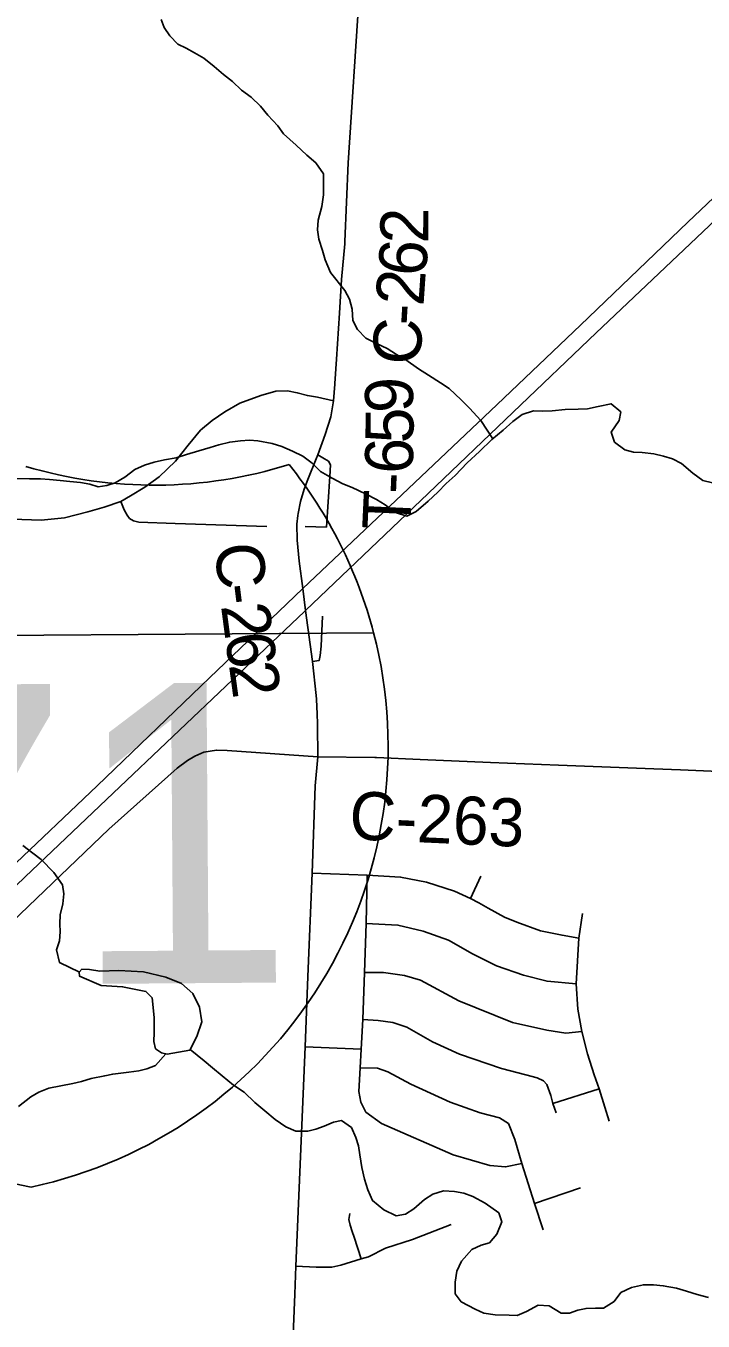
# Model space of a CAD drawing. Extents: x 114604 to 551442, y 316898 to 567001.
# Drawn here: x 184266 to 188495, y 344546 to 352635 of the extents above; entities that cross this region are included whole.
import ezdxf

# ---------------------------------------------------------------- set-up
doc = ezdxf.new("R2010")
doc.units = 0
for name, color, linetype in [('GE_P_Alignment', 7, 'Continuous'), ('GE_P_Alignment_1000_Cardinal_Points', 7, 'Continuous'), ('GE_P_Alignment_100_Cardinal_Points', 7, 'Continuous'), ('GE_P_Alignment_500_Bearings', 7, 'Continuous'), ('GE_P_Alignment_500_Stations', 7, 'Continuous'), ('MT_X_Edge_Line', 7, 'Continuous'), ('PM_P_Cells', 7, 'Continuous'), ('PM_P_CL_Double_Solid', 7, 'Continuous'), ('PM_P_Crosswalk', 7, 'Continuous'), ('PM_X_Stop_Line', 7, 'Continuous')]:
    doc.layers.add(name, color=color, linetype=linetype)

msp = doc.modelspace()

# ---------------------------------------------------------------- linework, layer by layer
at = {"layer": 'GE_P_Alignment'}
for p, q in [((182108.8, 348813.2), (186437.4, 348844.4)), ((186437.4, 348844.4), (182108.8, 348813.2)), ((186437.4, 348844.4), (182108.8, 348813.2))]:
    msp.add_line(p, q, dxfattribs=at)
for centre, start, end in [((185068, 352579.4), 253.42198, 287.40383), ((183715.5, 348135.1), 14.60627, 38.74396), ((184840.6, 348143.2), 166.21952, 258.87591), ((183715.5, 348135.1), 281.94987, 14.60626)]:
    msp.add_arc(centre, 2812.7, start, end, dxfattribs=at)
at = {"layer": 'GE_P_Alignment_1000_Cardinal_Points'}
msp.add_line((186010.5, 349509.4), (186142.5, 349503.5), dxfattribs=at)
for points in [[(186142.5, 349503.5), (186162.9, 349821.6), (186167.1, 349894.3), (186154.7, 349915.6), (186120.8, 349936.8), (186089.1, 349956.4)], [(186056.5, 348666), (186097.3, 348671.5), (186104, 348703.6), (186109.6, 348761), (186117.8, 348949.4)]]:
    msp.add_lwpolyline(points, dxfattribs=at)
at = {"layer": 'GE_P_Alignment_100_Cardinal_Points'}
for p, q in [((187042, 347184.6), (187106.8, 347325.2)), ((186009.6, 346258.3), (186358.7, 346245.2)), ((187556.9, 345905.7), (187846.2, 345996.4)), ((187442.7, 345281.3), (187729.1, 345377.4))]:
    msp.add_line(p, q, dxfattribs=at)
for points in [[(184859.5, 349665.4), (184880.1, 349612.7), (184897.1, 349579.2), (184913, 349559.3), (184937.3, 349544.8), (184971, 349535.6), (185197.9, 349527.8), (185769.5, 349508.8)], [(182825.3, 344498.5), (183312.3, 345163.3), (183352.2, 345250.6), (183357.3, 345349.2), (183381, 345685.8), (183381.3, 346045.3), (183386.5, 346123.7), (183420.8, 346199.3), (184129.2, 346991), (184784.2, 347618.1), (185210.8, 347999.8), (185274.8, 348047), (185321.4, 348074.7), (185377.9, 348098.5), (185455.8, 348112.7), (185522.2, 348109.3), (186088.3, 348070.5)], [(186053, 347342.9), (186397.5, 347331.9), (186605.9, 347318.6), (186767, 347286.4), (186942.3, 347231.3), (187042, 347184.6), (187094.1, 347158.3), (187152.9, 347125.3), (187254.9, 347069.7), (187332.2, 347038.3), (187479.4, 346983), (187614.5, 346955.8), (187718.6, 346937)], [(187363.5, 345530.9), (187261.6, 345509.1), (187162.3, 345517.4), (186933.5, 345584.9), (186487.5, 345780), (186387.8, 345851.4), (186357.3, 345914.4), (186344.8, 345980.4), (186352.7, 346127.7), (186358.7, 346245.2), (186370.4, 346430.1), (186381.5, 346723), (186391.2, 347029.3), (186397.5, 347331.9)], [(187907.7, 345795.5), (187881.5, 345882.5), (187846.2, 345996.4), (187814, 346083.4), (187774, 346215.3), (187738.4, 346354.8), (187713.4, 346494.4), (187702.1, 346652.3), (187718.6, 346937), (187742.9, 347092.6)], [(186391.2, 347029.3), (186589.7, 347019.1), (186746.2, 346981.1), (186905.8, 346925.2), (187054.4, 346839.8), (187204.4, 346765), (187373.1, 346706.1), (187520.6, 346668.1), (187702.1, 346652.3)], [(186381.5, 346723), (186498.7, 346723.8), (186631, 346703.8), (186730.4, 346674.4), (186968.7, 346546.9), (187303.9, 346411.8), (187519, 346363.8), (187637.9, 346345.1), (187738.4, 346354.8)], [(187576.8, 345847.2), (187556.9, 345905.7), (187544.5, 345955.2), (187518.5, 346024.1), (187498.8, 346046.5), (187459.6, 346065.8), (187387.4, 346083.3), (187236.9, 346122.8), (186974.8, 346212.6), (186805.2, 346290.3), (186645.3, 346382.3), (186558, 346411.7), (186464.8, 346423), (186370.4, 346430.1)], [(186352.7, 346127.7), (186460.9, 346125.5), (186527.2, 346101.9), (186668.9, 346024.8), (186916.1, 345912.4), (187102.9, 345847.6), (187223.3, 345815.4), (187280.6, 345779.7), (187320.4, 345680.9), (187363.5, 345530.9), (187442.7, 345281.3), (187496.7, 345116.9)], [(186359.4, 344936), (186315.1, 345070.3), (186303.5, 345106.6), (186290.2, 345145.6), (186283, 345181.1), (186287.9, 345217.6)], [(185952.6, 344888.8), (186078.6, 344882.7), (186176.6, 344883.5), (186232.1, 344896), (186359.4, 344936), (186404.5, 344948.5), (186511.7, 345001.6), (186680.3, 345055.3), (186921.3, 345149.9)]]:
    msp.add_lwpolyline(points, dxfattribs=at)
at = {"layer": 'GE_P_Alignment_500_Bearings'}
msp.add_line((186190.3, 350345.5), (186194.4, 350397.2), dxfattribs=at)
for points in [[(186256.7, 351272.9), (186258.1, 351288.3), (186278.9, 351779.8), (186346.8, 352826.4), (186359.9, 353064.4), (186410.9, 353932.9), (186445.3, 354455.2), (186507.1, 355361.3)], [(186194.4, 350397.2), (186194.8, 350402.4), (186206.1, 350553.5), (186224, 350841), (186237.2, 351051.2), (186256.7, 351272.9)], [(184859.5, 349665.4), (184919.8, 349700.1), (185009.2, 349754), (185097, 349818.9), (185199.7, 349916.4), (185279, 350017.1), (185355.1, 350109.4), (185428, 350171.6), (185507.7, 350225.6), (185602.4, 350279.6), (185732.2, 350327.3), (185827.1, 350353), (185898.8, 350356.8), (185960.6, 350343.9), (186024.1, 350326), (186085.9, 350316.5), (186186.1, 350293.8)], [(186078.9, 349931.6), (186089.1, 349956.4), (186135.7, 350082.4), (186170.2, 350193.6), (186186.1, 350293.8), (186190.3, 350345.5)], [(185964.4, 349578), (185965.6, 349589), (185980.7, 349664.6), (186004, 349741.6), (186025.7, 349803), (186078.9, 349931.6)], [(183871.6, 349564.2), (183876.9, 349564.1), (184359.9, 349548.4), (184506.6, 349562.8), (184653.2, 349600.5), (184754.7, 349629.6), (184859.5, 349665.4)], [(186078.5, 348452.2), (186056.5, 348666), (186012.8, 348985), (185994.9, 349120.9), (185972.1, 349293), (185960.7, 349424), (185958.4, 349522.8), (185964.4, 349578)], [(186088, 348124.5), (186087.5, 348216.5), (186086.9, 348277.8), (186085.3, 348337), (186080.7, 348430.9), (186078.5, 348452.2)], [(185924.6, 344204.5), (185945.2, 344713.4), (185952.6, 344888.8), (186009.6, 346258.3), (186025.5, 346698.5), (186053, 347342.9), (186072.5, 347890), (186088.3, 348070.5), (186088, 348124.5)], [(186088.3, 348070.5), (186444.7, 348066.4), (186455.2, 348066)], [(186455.2, 348066), (186728.8, 348054.2), (187166.6, 348033.8), (187591.7, 348017.5), (188187.4, 347995.2)], [(188187.4, 347995.2), (188354.7, 347988.9), (189023.3, 347960.2), (189329, 347950.5), (190166.3, 347908.4), (190917.1, 347857.4), (191544.9, 347823.3)]]:
    msp.add_lwpolyline(points, dxfattribs=at)
at = {"layer": 'GE_P_Alignment_500_Stations'}
for points in [[(185895.9, 349026.3), (185994.9, 349120.9), (186653.2, 349744), (187209.8, 350270), (187729.5, 350766), (188400.5, 351410), (188722.5, 351715.3)], [(186005.2, 348977.7), (186012.8, 348985), (186777.7, 349715.4), (187308.6, 350222.7), (187828.4, 350718.6), (188612.6, 351460.8), (188833.9, 351672.2)], [(183841.4, 347059.4), (183867.5, 347085.5), (184162.5, 347368.7), (184710.9, 347889.9), (185412.6, 348564.3), (185895.9, 349026.3)], [(183940.3, 347012), (183966.3, 347038.2), (184261.4, 347321.4), (184809.8, 347842.6), (185556.2, 348551.9), (186005.2, 348977.7)]]:
    msp.add_lwpolyline(points, dxfattribs=at)
at = {"layer": 'MT_X_Edge_Line'}
for points in [[(185288.9, 346238.4), (185333, 346322.5), (185365.2, 346414.6), (185349.3, 346506.8), (185307.4, 346591.1), (185237.5, 346655.3), (185139.5, 346693.5), (184999.4, 346727.8), (184845.3, 346736), (184727.3, 346732.2), (184663.2, 346742.3), (184615.2, 346744.3), (184599.1, 346724.3), (184601.1, 346700.3), (184735.1, 346642), (184869.2, 346633.8), (185015.2, 346605.5), (185053.2, 346565.4), (185067, 346443.1), (185066.9, 346348.9), (185064.8, 346292.8), (185074.7, 346246.7), (185112.7, 346220.6), (185148.7, 346212.5)], [(185148.7, 346212.5), (185288.9, 346238.4)]]:
    msp.add_lwpolyline(points, dxfattribs=at)
at = {"layer": 'PM_P_Cells'}
for points in [[(187182.5, 350056.7), (187146, 350109.5), (187108.1, 350169.7), (187036.2, 350248), (186984.2, 350300.1), (186910.3, 350370.4), (186854.3, 350406.6), (186780.3, 350452.7), (186718.3, 350492.9), (186638.4, 350549.1), (186580.4, 350583.3), (186522.4, 350619.5), (186456.4, 350651.6), (186388.4, 350685.8), (186336.5, 350738), (186308.5, 350794.1), (186302.6, 350866.3), (186286.7, 350928.4), (186256.8, 350982.6), (186168.9, 351094.9), (186135, 351173.1), (186117.1, 351231.3), (186095.1, 351303.4), (186087.2, 351361.6), (186091.3, 351421.7), (186113.5, 351507.8), (186123.6, 351579.9), (186123.8, 351710.2), (186075.9, 351780.4), (186019.9, 351828.6), (185953.9, 351890.8), (185874, 351961.1), (185838.1, 352011.2), (185776.1, 352077.4), (185730.2, 352133.6), (185672.2, 352189.8), (185612.2, 352234), (185556.3, 352288.2), (185500.3, 352332.3), (185442.4, 352380.5), (185376.4, 352432.7), (185318.4, 352466.8), (185266.4, 352495), (185214.4, 352521.1), (185164.5, 352573.3), (185128.5, 352625.4), (185110.6, 352675.6)], [(188554.5, 349780.8), (188494.5, 349794.9), (188430.5, 349841.1), (188360.5, 349901.3), (188304.5, 349931.5), (188248.5, 349947.6), (188188.5, 349961.7), (188114.5, 349969.8), (188060.4, 349971.9), (188006.4, 349988), (187942.5, 350036.2), (187920.5, 350098.4), (187970.7, 350170.5), (187980.8, 350224.6), (187920.8, 350274.7), (187840.7, 350258.8), (187772.7, 350242.9), (187714.6, 350241), (187634.6, 350239.1), (187552.5, 350231.2), (187492.5, 350229.3), (187436.4, 350231.4), (187366.3, 350207.4), (187306.2, 350163.4), (187246.1, 350109.4), (187176, 350051.4), (187099.8, 349977.3), (187021.6, 349905.3), (186947.5, 349827.2), (186891.4, 349777.2), (186839.2, 349723.2), (186777.1, 349667.2), (186703, 349603.2), (186644.9, 349573.2), (186574.9, 349595.3), (186508.9, 349643.5), (186454.9, 349677.7), (186386.9, 349711.8), (186302.9, 349752), (186244.9, 349774.2), (186178.9, 349810.3), (186104.9, 349852.5), (186053, 349904.7), (185995, 349946.9), (185931, 349979), (185865, 350009.2), (185803, 350027.3), (185715, 350043.4), (185662.9, 350047.5), (185604.9, 350043.6)], [(185604.9, 350043.6), (185538.8, 350035.7), (185470.8, 350017.7), (185416.7, 350001.8), (185346.6, 349981.8), (185268.5, 349957.9), (185204.5, 349938), (185130.4, 349924), (185066.3, 349910.1), (185006.3, 349892.1), (184946.2, 349864.2), (184884.1, 349816.2), (184824, 349782.2), (184771.9, 349764.2), (184715.9, 349756.3), (184663.9, 349772.4), (184605.8, 349782.5), (184539.8, 349790.6), (184479.7, 349796.7), (184413.7, 349802.8), (184357.7, 349806.9), (184287.6, 349807), (184209.6, 349809.1)], [(184600.3, 346725.7), (184475.2, 346786.6), (184457.3, 346864.8), (184475.4, 346920.9), (184479.4, 346977), (184477.5, 347027.1), (184479.6, 347083.2), (184495.7, 347151.3), (184501.8, 347215.5), (184493.9, 347271.6), (184440, 347347.8), (184360.1, 347428.1), (184308.1, 347468.2), (184246.1, 347516.4)], [(185139.1, 346214.7), (185074.6, 346142.5), (185020.5, 346122.5), (184970.5, 346108.6), (184908.4, 346100.6), (184808.3, 346088.8), (184758.3, 346078.8), (184672.2, 346060.9), (184612.1, 346042.9), (184558.1, 346031), (184407.9, 346001.1), (184345.8, 345975.2), (184295.7, 345947.2), (184219.6, 345887.2)], [(187607.9, 344595.7), (187533.9, 344641.9), (187465.9, 344646), (187391.8, 344606.1), (187333.7, 344580.1), (187283.7, 344582.2), (187197.6, 344584.3), (187125.6, 344596.4), (187071.6, 344620.5), (186983.6, 344666.8), (186947.7, 344716.9), (186945.8, 344789.1), (186957.9, 344857.2), (186986, 344921.3), (187050.2, 344993.3), (187110.2, 345019.3), (187160.3, 345035.3), (187206.4, 345089.3), (187238.5, 345165.4), (187218.6, 345221.6), (187134.7, 345281.8), (187056.7, 345324), (187000.7, 345344.1), (186942.6, 345356.2), (186874.6, 345360.3), (186806.5, 345338.4), (186754.4, 345306.4), (186688.3, 345246.4), (186636.2, 345214.4), (186578.2, 345202.5), (186500.2, 345240.6), (186430.2, 345298.9), (186400.3, 345365), (186380.4, 345433.2), (186364.5, 345505.4), (186350.6, 345585.5), (186342.7, 345639.7), (186326.7, 345691.8), (186298.8, 345756), (186236.8, 345798.2), (186186.8, 345788.2), (186128.7, 345764.2), (186076.6, 345744.3), (186026.6, 345732.3), (185952.5, 345732.4), (185888.5, 345758.6), (185822.6, 345804.7), (185758.6, 345859), (185694.6, 345911.1), (185628.7, 345975.4), (185562.7, 346019.6), (185490.8, 346077.8), (185430.8, 346128), (185378.8, 346172.1), (185290.6, 346241.6)], [(188528.7, 344692.6), (188458.7, 344712.7), (188392.7, 344732.9), (188328.7, 344751), (188246.6, 344767.2), (188184.6, 344773.3), (188122.5, 344773.3), (188048.5, 344755.4), (187982.4, 344725.5), (187940.3, 344669.4), (187874.2, 344627.4), (187824.1, 344627.5), (187764.1, 344625.6), (187712, 344613.6), (187660, 344595.6), (187607.9, 344595.7)]]:
    msp.add_lwpolyline(points, dxfattribs=at)

# ---------------------------------------------------------------- texts
at = {"layer": 'GE_P_Alignment'}
msp.add_text('71', height=1875.14, rotation=0.41289, dxfattribs=at).set_placement((183160.5, 346641))
at = {"layer": 'PM_P_CL_Double_Solid'}
for s, height, rotation, p in [('2', 300, 89.66517, (186778.9, 351275.7)), ('6', 300, 84.87271, (186761.1, 351064.2)), ('2', 300, 86.11043, (186748.7, 350881.6)), ('-', 300, 86.78062, (186741.8, 350759.5)), ('C', 300, 86.94495, (186728.7, 350513.6)), ('C', 300, 275.11337, (185444.8, 349395.7)), ('-', 300, 277.13353, (185468, 349138.8)), ('2', 300, 277.55918, (185483.6, 349014.1)), ('6', 300, 277.73058, (185508.1, 348829.9)), ('2', 300, 277.77228, (185532.9, 348646.5)), ('C-263', 300.02, 357.3855, (186281.2, 347556.6))]:
    msp.add_text(s, height=height, rotation=rotation, dxfattribs=at).set_placement(p)
at = {"layer": 'PM_P_Crosswalk'}
for s, rotation, p in [('9', 91.66409, (186687, 350223.3)), ('5', 89.74006, (186686.3, 350027.5)), ('6', 88.41668, (186681, 349835.2)), ('-', 87.61193, (186675.7, 349707.5)), ('T', 87.36006, (186665.4, 349481.9))]:
    msp.add_text(s, height=300, rotation=rotation, dxfattribs=at).set_placement(p)
at = {"layer": 'PM_X_Stop_Line'}
for s in ['-', '.', ',']:
    msp.add_text(s, height=1, rotation=0.41289, dxfattribs=at).set_placement((184281.6, 347633))

doc.saveas('drawing.dxf')
